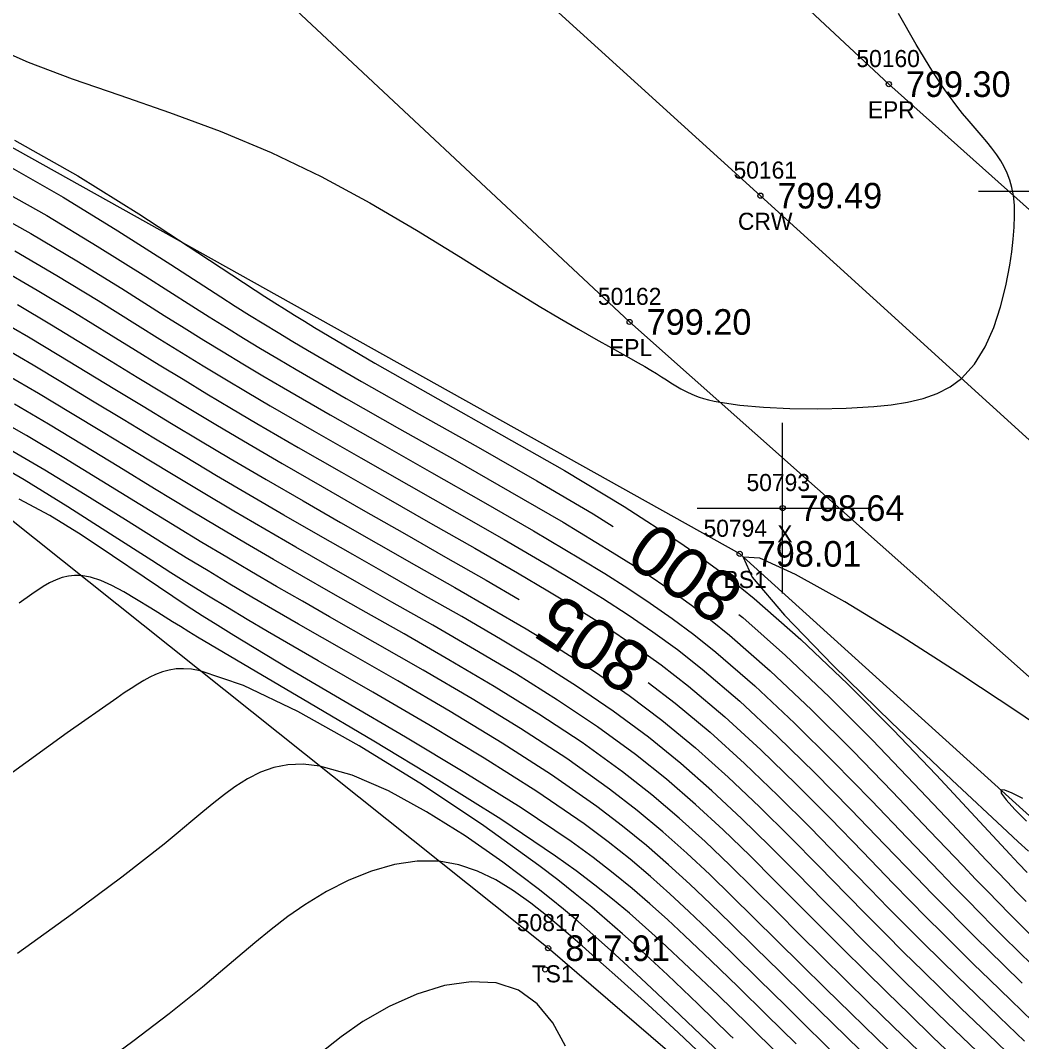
# Model space of a CAD drawing. Extents: x 1378535 to 1380697, y 997729 to 1000024.
# Drawn here: x 1378608.7 to 1378667.4, y 999849.2 to 999909.1 of the extents above; entities that cross this region are included whole.
import ezdxf

# ---------------------------------------------------------------- set-up
doc = ezdxf.new("R2010")
doc.units = 0
for name, color, linetype in [('RD_DTM_BkLn1', 7, 'Continuous'), ('RD_DTM_BkLn2', 7, 'Continuous'), ('RD_DTM_BkLn_txCode', 7, 'Continuous'), ('RD_DTM_Major1', 7, 'Continuous'), ('RD_DTM_Major1_Lbl', 7, 'Continuous'), ('RD_DTM_Minor1', 7, 'Continuous'), ('RD_EX_Misc', 7, 'Continuous'), ('RD_EX_Misc_txCode', 7, 'Continuous'), ('RD_EX_Road', 7, 'Continuous'), ('RD_EX_Road_txCode', 7, 'Continuous'), ('RD_EX_TX_Misc_ELEV', 7, 'Continuous'), ('RD_EX_TX_Road_ELEV', 7, 'Continuous'), ('RD_HC_Survey_ELEV', 7, 'Continuous'), ('RD_HC_Survey_txCode', 7, 'Continuous'), ('RD_SMD_Locator', 7, 'Continuous')]:
    doc.layers.add(name, color=color, linetype=linetype)

msp = doc.modelspace()

# ---------------------------------------------------------------- linework, layer by layer
at = {"layer": 'RD_DTM_BkLn1'}
msp.add_lwpolyline([(1379201.7, 999398.205), (1379156.533, 999438.891), (1379112.084, 999479.847), (1379066.495, 999520.561), (1379020.821, 999562.613), (1378974.239, 999604.981), (1378928.957, 999646.778), (1378882.739, 999688.619), (1378834.578, 999733.071), (1378787.698, 999775.121), (1378743.642, 999816.274), (1378698.706, 999856.431), (1378652.056, 999898.787), (1378607.023, 999939.646), (1378604.538, 999941.267)], dxfattribs=at)
at = {"layer": 'RD_DTM_BkLn2'}
for points in [[(1378760.972, 999750.758), (1378735.038, 999800.678), (1378693.628, 999839.142), (1378650.843, 999877.81), (1378599.986, 999906.202), (1378575.293, 999908.279)], [(1378753.21, 999744.316), (1378718.796, 999791.159), (1378676.682, 999822.843), (1378639.622, 999854.713), (1378600.054, 999886.249), (1378588.163, 999885.418), (1378551.81, 999886.228), (1378537.215, 999880.675)]]:
    msp.add_lwpolyline(points, dxfattribs=at)
at = {"layer": 'RD_DTM_Major1'}
for points in [[(1378607.923, 999900.565), (1378611.205, 999898.707), (1378614.415, 999896.737), (1378617.508, 999894.754), (1378620.441, 999892.862), (1378621.289, 999892.323), (1378622.128, 999891.797), (1378622.963, 999891.279), (1378623.804, 999890.765), (1378624.658, 999890.25), (1378625.532, 999889.73), (1378628.688, 999887.904), (1378632.057, 999886), (1378635.52, 999884.05), (1378638.958, 999882.089), (1378642.252, 999880.149), (1378643.423, 999879.421)], [(1378608.533, 999892.407), (1378610.521, 999891.23), (1378612.479, 999890.037), (1378614.016, 999889.096), (1378615.537, 999888.167), (1378617.058, 999887.242), (1378618.594, 999886.314), (1378620.161, 999885.376), (1378621.776, 999884.421), (1378624.039, 999883.101), (1378626.386, 999881.75), (1378628.785, 999880.378), (1378631.206, 999878.999), (1378633.617, 999877.624), (1378635.987, 999876.266), (1378637.925, 999875.145)], [(1378660.491, 999847.861), (1378658.882, 999849.416), (1378657.346, 999850.912), (1378655.87, 999852.358), (1378654.441, 999853.763), (1378653.048, 999855.139), (1378651.677, 999856.495), (1378650.392, 999857.762), (1378649.09, 999859.023), (1378647.747, 999860.279), (1378646.338, 999861.532), (1378644.838, 999862.784), (1378643.221, 999864.037), (1378640.707, 999865.815), (1378637.994, 999867.58), (1378635.164, 999869.313), (1378632.301, 999870.995), (1378629.489, 999872.606), (1378626.813, 999874.127), (1378625.232, 999875.029), (1378623.716, 999875.903), (1378622.243, 999876.76), (1378620.79, 999877.616), (1378619.337, 999878.483), (1378617.861, 999879.376), (1378615.692, 999880.707), (1378613.475, 999882.074), (1378611.251, 999883.432), (1378609.062, 999884.736), (1378606.949, 999885.941)], [(1378650.79, 999874.265), (1378651.025, 999874.073), (1378653.534, 999871.862), (1378656.093, 999869.426), (1378658.624, 999866.888), (1378661.052, 999864.368), (1378663.3, 999861.991), (1378665.292, 999859.877), (1378665.922, 999859.214), (1378666.518, 999858.592), (1378667.086, 999858.003), (1378667.635, 999857.44)], [(1378650.457, 999849.444), (1378650.275, 999849.622), (1378648.411, 999851.431), (1378646.608, 999853.148), (1378644.834, 999854.787), (1378643.968, 999855.564), (1378643.086, 999856.335), (1378642.172, 999857.11), (1378641.21, 999857.898), (1378640.184, 999858.709), (1378639.079, 999859.552), (1378635.856, 999861.871), (1378632.259, 999864.275), (1378628.545, 999866.574), (1378624.966, 999868.581), (1378621.779, 999870.106), (1378619.236, 999870.961), (1378618.724, 999871.049), (1378618.258, 999871.085), (1378617.826, 999871.069), (1378617.417, 999871.005), (1378617.019, 999870.895), (1378616.621, 999870.739), (1378616.286, 999870.58), (1378615.94, 999870.391), (1378615.577, 999870.176), (1378615.194, 999869.932), (1378614.787, 999869.662), (1378614.351, 999869.366), (1378611.445, 999867.325), (1378607.81, 999864.7)], [(1378645.487, 999870.273), (1378647.062, 999869.072), (1378649.115, 999867.357), (1378651.124, 999865.538), (1378653.079, 999863.663), (1378654.965, 999861.779), (1378656.77, 999859.933), (1378658.481, 999858.174), (1378659.55, 999857.083), (1378660.586, 999856.037), (1378661.601, 999855.022), (1378662.609, 999854.025), (1378663.621, 999853.032), (1378664.651, 999852.031), (1378666.061, 999850.672), (1378667.522, 999849.271)]]:
    msp.add_lwpolyline(points, dxfattribs=at)
at = {"layer": 'RD_DTM_Minor1'}
for points in [[(1378606.804, 999907.633), (1378609.149, 999906.606), (1378611.741, 999905.636), (1378614.521, 999904.673), (1378617.429, 999903.666), (1378620.405, 999902.566), (1378623.388, 999901.323), (1378626.323, 999899.905), (1378629.174, 999898.362), (1378631.908, 999896.763), (1378634.494, 999895.177), (1378636.899, 999893.673), (1378639.09, 999892.32), (1378640.288, 999891.607), (1378641.397, 999890.967), (1378642.415, 999890.392), (1378643.34, 999889.876), (1378644.17, 999889.413), (1378644.905, 999888.996), (1378645.284, 999888.775), (1378645.635, 999888.565), (1378645.96, 999888.368), (1378646.263, 999888.181), (1378646.547, 999888.003), (1378646.815, 999887.835), (1378647.011, 999887.713), (1378647.204, 999887.596), (1378647.395, 999887.484), (1378647.59, 999887.376), (1378647.789, 999887.274), (1378647.998, 999887.176), (1378648.223, 999887.082), (1378648.465, 999886.992), (1378648.729, 999886.908), (1378649.019, 999886.829), (1378649.34, 999886.754), (1378649.696, 999886.685), (1378650.854, 999886.521), (1378652.241, 999886.399), (1378653.787, 999886.324), (1378655.425, 999886.301), (1378657.085, 999886.337), (1378658.699, 999886.437), (1378659.72, 999886.544), (1378660.684, 999886.697), (1378661.585, 999886.912), (1378662.416, 999887.205), (1378663.171, 999887.59), (1378663.845, 999888.083), (1378664.609, 999888.92), (1378665.234, 999889.927), (1378665.735, 999891.059), (1378666.13, 999892.268), (1378666.434, 999893.507), (1378666.664, 999894.727), (1378666.781, 999895.499), (1378666.87, 999896.239), (1378666.928, 999896.943), (1378666.95, 999897.608), (1378666.935, 999898.229), (1378666.877, 999898.803), (1378666.79, 999899.268), (1378666.67, 999899.698), (1378666.519, 999900.1), (1378666.341, 999900.478), (1378666.136, 999900.838), (1378665.908, 999901.185), (1378665.625, 999901.566), (1378665.319, 999901.946), (1378664.99, 999902.332), (1378664.643, 999902.733), (1378664.28, 999903.155), (1378663.904, 999903.608), (1378663.63, 999903.951), (1378663.351, 999904.316), (1378663.065, 999904.705), (1378662.772, 999905.12), (1378662.471, 999905.564), (1378662.161, 999906.038), (1378661.188, 999907.636), (1378660.151, 999909.464)], [(1378608.358, 999902.033), (1378612.063, 999899.957), (1378615.64, 999897.73), (1378619.099, 999895.46), (1378622.45, 999893.256), (1378623.029, 999892.884), (1378623.606, 999892.517), (1378624.183, 999892.153), (1378624.763, 999891.791), (1378625.346, 999891.431), (1378625.935, 999891.072), (1378629.476, 999888.986), (1378633.164, 999886.891), (1378636.896, 999884.79), (1378640.57, 999882.685), (1378644.084, 999880.577), (1378647.335, 999878.47), (1378648.089, 999877.947), (1378648.825, 999877.421), (1378649.549, 999876.887), (1378650.263, 999876.341), (1378650.974, 999875.78), (1378651.685, 999875.2), (1378654.422, 999872.803), (1378657.161, 999870.198), (1378659.828, 999867.51), (1378662.35, 999864.867), (1378664.655, 999862.397), (1378666.67, 999860.226), (1378667.186, 999859.673), (1378667.678, 999859.151)], [(1378607.27, 999899.293), (1378610.26, 999897.619), (1378613.207, 999895.839), (1378616.052, 999894.047), (1378618.738, 999892.336), (1378619.764, 999891.69), (1378620.769, 999891.064), (1378621.767, 999890.45), (1378622.772, 999889.84), (1378623.799, 999889.226), (1378624.861, 999888.599), (1378627.78, 999886.915), (1378630.914, 999885.138), (1378634.153, 999883.309), (1378637.384, 999881.469), (1378640.497, 999879.657), (1378643.38, 999877.915), (1378644.609, 999877.142), (1378645.782, 999876.376), (1378646.915, 999875.6), (1378648.027, 999874.798), (1378649.132, 999873.953), (1378650.248, 999873.049), (1378652.626, 999870.965), (1378655.054, 999868.668), (1378657.466, 999866.266), (1378659.793, 999863.869), (1378661.97, 999861.587), (1378663.928, 999859.529), (1378664.662, 999858.765), (1378665.355, 999858.049), (1378666.017, 999857.372), (1378666.656, 999856.723), (1378667.282, 999856.095), (1378667.903, 999855.477)], [(1378606.59, 999898.08), (1378609.314, 999896.578), (1378612.017, 999894.972), (1378614.641, 999893.343), (1378617.13, 999891.775), (1378618.303, 999891.041), (1378619.448, 999890.331), (1378620.582, 999889.636), (1378621.726, 999888.944), (1378622.897, 999888.245), (1378624.115, 999887.529), (1378626.848, 999885.95), (1378629.773, 999884.285), (1378632.796, 999882.572), (1378635.824, 999880.848), (1378638.763, 999879.152), (1378641.52, 999877.52), (1378642.942, 999876.652), (1378644.299, 999875.795), (1378645.608, 999874.928), (1378646.89, 999874.029), (1378648.164, 999873.077), (1378649.447, 999872.052), (1378651.729, 999870.071), (1378654.045, 999867.899), (1378656.341, 999865.631), (1378658.563, 999863.36), (1378660.656, 999861.18), (1378662.567, 999859.185), (1378663.395, 999858.328), (1378664.181, 999857.523), (1378664.934, 999856.759), (1378665.664, 999856.025), (1378666.383, 999855.31), (1378667.1, 999854.603), (1378668.064, 999853.662)], [(1378608.378, 999895.556), (1378610.842, 999894.116), (1378613.252, 999892.641), (1378615.561, 999891.201), (1378616.866, 999890.389), (1378618.14, 999889.603), (1378619.404, 999888.831), (1378620.679, 999888.061), (1378621.985, 999887.282), (1378623.343, 999886.483), (1378625.912, 999884.995), (1378628.639, 999883.437), (1378631.451, 999881.838), (1378634.275, 999880.231), (1378637.04, 999878.644), (1378639.673, 999877.108), (1378641.278, 999876.151), (1378642.815, 999875.205), (1378644.302, 999874.247), (1378645.758, 999873.252), (1378647.2, 999872.198), (1378648.645, 999871.061), (1378650.847, 999869.172), (1378653.059, 999867.12), (1378655.24, 999864.984), (1378657.352, 999862.841), (1378659.353, 999860.769), (1378661.206, 999858.845), (1378662.121, 999857.903), (1378662.994, 999857.014), (1378663.836, 999856.165), (1378664.658, 999855.344), (1378665.472, 999854.539), (1378666.29, 999853.738), (1378667.395, 999852.665)], [(1378607.451, 999894.54), (1378609.68, 999893.263), (1378611.879, 999891.938), (1378614.013, 999890.621), (1378615.439, 999889.741), (1378616.838, 999888.882), (1378618.23, 999888.033), (1378619.634, 999887.185), (1378621.071, 999886.327), (1378622.561, 999885.448), (1378624.976, 999884.046), (1378627.51, 999882.591), (1378630.114, 999881.107), (1378632.736, 999879.614), (1378635.325, 999878.134), (1378637.83, 999876.689), (1378639.608, 999875.646), (1378641.325, 999874.611), (1378642.995, 999873.559), (1378644.63, 999872.467), (1378646.244, 999871.311), (1378647.85, 999870.068), (1378649.977, 999868.266), (1378652.087, 999866.332), (1378654.154, 999864.327), (1378656.154, 999862.313), (1378658.058, 999860.353), (1378659.844, 999858.508), (1378660.839, 999857.489), (1378661.795, 999856.519), (1378662.724, 999855.586), (1378663.639, 999854.678), (1378664.551, 999853.78), (1378665.473, 999852.881), (1378666.728, 999851.668), (1378668.025, 999850.422)], [(1378607.401, 999891.544), (1378609.178, 999890.514), (1378610.955, 999889.45), (1378612.594, 999888.457), (1378614.235, 999887.46), (1378615.886, 999886.458), (1378617.556, 999885.448), (1378619.254, 999884.429), (1378620.989, 999883.4), (1378623.101, 999882.163), (1378625.263, 999880.912), (1378627.463, 999879.651), (1378629.685, 999878.383), (1378631.918, 999877.112), (1378634.146, 999875.842), (1378636.248, 999874.636), (1378638.328, 999873.418), (1378640.378, 999872.169), (1378642.392, 999870.873), (1378644.362, 999869.513), (1378646.282, 999868.072), (1378648.257, 999866.444), (1378650.167, 999864.739), (1378652.009, 999862.993), (1378653.783, 999861.238), (1378655.486, 999859.509), (1378657.118, 999857.84), (1378658.255, 999856.685), (1378659.368, 999855.566), (1378660.468, 999854.47), (1378661.569, 999853.384), (1378662.684, 999852.293), (1378663.826, 999851.186), (1378665.397, 999849.674), (1378667.028, 999848.114)], [(1378664.735, 999848.676), (1378662.997, 999850.345), (1378661.741, 999851.562), (1378660.521, 999852.752), (1378659.326, 999853.929), (1378658.142, 999855.105), (1378656.957, 999856.293), (1378655.755, 999857.506), (1378654.207, 999859.08), (1378652.605, 999860.692), (1378650.942, 999862.319), (1378649.211, 999863.939), (1378647.402, 999865.53), (1378645.508, 999867.068), (1378643.435, 999868.601), (1378641.281, 999870.064), (1378639.07, 999871.466), (1378636.822, 999872.818), (1378634.56, 999874.132), (1378632.306, 999875.416), (1378630.228, 999876.597), (1378628.175, 999877.765), (1378626.146, 999878.924), (1378624.142, 999880.078), (1378622.16, 999881.23), (1378620.2, 999882.383), (1378618.351, 999883.487), (1378616.522, 999884.588), (1378614.716, 999885.682), (1378612.933, 999886.762), (1378611.174, 999887.823), (1378609.442, 999888.858), (1378607.853, 999889.789)], [(1378664.077, 999847.681), (1378662.168, 999849.512), (1378660.794, 999850.84), (1378659.469, 999852.131), (1378658.179, 999853.398), (1378656.912, 999854.652), (1378655.655, 999855.906), (1378654.394, 999857.172), (1378652.931, 999858.646), (1378651.431, 999860.14), (1378649.877, 999861.641), (1378648.255, 999863.137), (1378646.548, 999864.614), (1378644.74, 999866.061), (1378642.516, 999867.681), (1378640.177, 999869.246), (1378637.763, 999870.757), (1378635.313, 999872.216), (1378632.869, 999873.626), (1378630.47, 999874.989), (1378628.549, 999876.078), (1378626.675, 999877.146), (1378624.835, 999878.2), (1378623.019, 999879.251), (1378621.215, 999880.305), (1378619.412, 999881.374), (1378617.451, 999882.551), (1378615.492, 999883.737), (1378613.547, 999884.918), (1378611.632, 999886.075), (1378609.76, 999887.194), (1378607.944, 999888.257)], [(1378661.332, 999848.683), (1378659.84, 999850.125), (1378658.409, 999851.518), (1378657.026, 999852.874), (1378655.678, 999854.205), (1378654.351, 999855.521), (1378653.035, 999856.835), (1378651.66, 999858.207), (1378650.26, 999859.584), (1378648.813, 999860.961), (1378647.298, 999862.334), (1378645.693, 999863.699), (1378643.978, 999865.051), (1378641.607, 999866.753), (1378639.081, 999868.419), (1378636.46, 999870.041), (1378633.805, 999871.61), (1378631.177, 999873.118), (1378628.638, 999874.558), (1378626.883, 999875.555), (1378625.187, 999876.525), (1378623.532, 999877.479), (1378621.899, 999878.429), (1378620.271, 999879.389), (1378618.628, 999880.371), (1378616.56, 999881.623), (1378614.471, 999882.898), (1378612.388, 999884.166), (1378610.339, 999885.399), (1378608.354, 999886.568)], [(1378657.917, 999848.716), (1378656.278, 999850.313), (1378654.711, 999851.847), (1378653.205, 999853.326), (1378651.746, 999854.758), (1378650.322, 999856.151), (1378649.128, 999857.311), (1378647.923, 999858.456), (1378646.681, 999859.593), (1378645.377, 999860.728), (1378643.982, 999861.868), (1378642.471, 999863.019), (1378639.821, 999864.865), (1378636.921, 999866.727), (1378633.881, 999868.571), (1378630.808, 999870.368), (1378627.81, 999872.087), (1378624.995, 999873.696), (1378623.6, 999874.501), (1378622.266, 999875.279), (1378620.972, 999876.043), (1378619.698, 999876.807), (1378618.422, 999877.582), (1378617.122, 999878.382), (1378614.851, 999879.8), (1378612.504, 999881.263), (1378610.133, 999882.71), (1378607.787, 999884.08)], [(1378656.934, 999847.987), (1378653.55, 999851.33), (1378651.969, 999852.888), (1378650.446, 999854.377), (1378648.97, 999855.807), (1378647.868, 999856.858), (1378646.759, 999857.889), (1378645.618, 999858.907), (1378644.419, 999859.924), (1378643.134, 999860.949), (1378641.738, 999861.991), (1378638.96, 999863.893), (1378635.882, 999865.84), (1378632.635, 999867.792), (1378629.349, 999869.707), (1378626.154, 999871.546), (1378623.182, 999873.267), (1378621.984, 999873.973), (1378620.835, 999874.66), (1378619.72, 999875.337), (1378618.619, 999876.016), (1378617.517, 999876.706), (1378616.396, 999877.419), (1378613.989, 999878.969), (1378611.482, 999880.572), (1378608.928, 999882.145), (1378606.38, 999883.603)], [(1378654.149, 999849.104), (1378652.408, 999850.82), (1378650.748, 999852.446), (1378649.156, 999853.987), (1378647.618, 999855.449), (1378646.606, 999856.389), (1378645.588, 999857.306), (1378644.54, 999858.212), (1378643.438, 999859.117), (1378642.257, 999860.032), (1378640.972, 999860.969), (1378638.038, 999862.939), (1378634.748, 999864.991), (1378631.261, 999867.075), (1378627.736, 999869.141), (1378624.331, 999871.141), (1378621.206, 999873.024), (1378620.261, 999873.612), (1378619.356, 999874.187), (1378618.481, 999874.752), (1378617.627, 999875.313), (1378616.786, 999875.875), (1378615.949, 999876.441), (1378614.106, 999877.7), (1378612.259, 999878.931), (1378610.43, 999880.061), (1378608.636, 999881.017)], [(1378668.865, 999867.369), (1378667.146, 999868.531), (1378663.851, 999870.714), (1378660.358, 999872.946), (1378657, 999874.991), (1378654.109, 999876.61), (1378652.017, 999877.566), (1378651.054, 999877.619), (1378651.566, 999876.446), (1378653.46, 999874.212), (1378656.321, 999871.262), (1378659.732, 999867.936), (1378663.277, 999864.578), (1378666.541, 999861.53), (1378667.163, 999860.951), (1378667.757, 999860.399)], [(1378653.162, 999848.446), (1378651.323, 999850.258), (1378649.573, 999851.965), (1378647.892, 999853.573), (1378646.261, 999855.088), (1378645.325, 999855.931), (1378644.378, 999856.757), (1378643.399, 999857.577), (1378642.366, 999858.402), (1378641.258, 999859.243), (1378640.055, 999860.112), (1378636.846, 999862.267), (1378633.226, 999864.541), (1378629.416, 999866.839), (1378625.641, 999869.067), (1378622.123, 999871.131), (1378619.085, 999872.937), (1378618.571, 999873.249), (1378618.081, 999873.548), (1378617.615, 999873.834), (1378616.746, 999874.371), (1378616.341, 999874.622), (1378615.511, 999875.132), (1378614.753, 999875.578), (1378614.057, 999875.952), (1378613.413, 999876.244), (1378612.809, 999876.443), (1378612.235, 999876.54), (1378611.872, 999876.545), (1378611.513, 999876.503), (1378611.153, 999876.416), (1378610.789, 999876.284), (1378610.416, 999876.109), (1378610.029, 999875.892), (1378609.364, 999875.454), (1378608.637, 999874.914)], [(1378651.085, 999847.256), (1378648.963, 999849.268), (1378646.969, 999851.158), (1378645.077, 999852.934), (1378643.265, 999854.599), (1378642.583, 999855.213), (1378641.902, 999855.814), (1378641.215, 999856.409), (1378640.514, 999857), (1378639.793, 999857.593), (1378639.044, 999858.19), (1378636.976, 999859.752), (1378634.765, 999861.287), (1378632.498, 999862.706), (1378630.262, 999863.921), (1378628.146, 999864.842), (1378626.237, 999865.381), (1378625.264, 999865.488), (1378624.372, 999865.454), (1378623.543, 999865.291), (1378622.761, 999865.014), (1378622.008, 999864.635), (1378621.269, 999864.167), (1378620.659, 999863.725), (1378620.034, 999863.235), (1378619.381, 999862.696), (1378618.686, 999862.112), (1378617.938, 999861.484), (1378617.122, 999860.812), (1378614.65, 999858.88), (1378611.748, 999856.723), (1378608.524, 999854.395)], [(1378667.434, 999863.485), (1378666.809, 999863.798), (1378666.37, 999863.97), (1378666.146, 999863.98), (1378666.172, 999863.787), (1378666.459, 999863.398), (1378666.967, 999862.843), (1378667.655, 999862.148)], [(1378649.064, 999848.054), (1378647.267, 999849.748), (1378645.461, 999851.408), (1378643.697, 999852.999), (1378642.023, 999854.486), (1378641.609, 999854.851), (1378641.204, 999855.206), (1378640.804, 999855.554), (1378640.409, 999855.893), (1378640.016, 999856.225), (1378639.625, 999856.55), (1378638.615, 999857.348), (1378637.593, 999858.078), (1378636.552, 999858.713), (1378635.484, 999859.229), (1378634.381, 999859.6), (1378633.237, 999859.802), (1378631.948, 999859.808), (1378630.622, 999859.61), (1378629.279, 999859.233), (1378627.941, 999858.699), (1378626.629, 999858.034), (1378625.362, 999857.262), (1378624.366, 999856.564), (1378623.394, 999855.815), (1378622.428, 999855.022), (1378621.447, 999854.188), (1378620.432, 999853.321), (1378619.362, 999852.424), (1378617.419, 999850.873), (1378615.288, 999849.252), (1378612.985, 999847.556)], [(1378640.634, 999848.976), (1378639.889, 999850.335), (1378638.98, 999851.45), (1378637.885, 999852.247), (1378636.582, 999852.676), (1378635.119, 999852.753), (1378633.551, 999852.521), (1378631.932, 999852.025), (1378630.316, 999851.307), (1378628.758, 999850.412), (1378627.486, 999849.526), (1378626.275, 999848.558)]]:
    msp.add_lwpolyline(points, dxfattribs=at)
at = {"layer": 'RD_EX_Misc'}
for p, q in [((1378664.831, 999899.048), (1378674.831, 999899.048)), ((1378653.361, 999875.488), (1378653.361, 999885.488)), ((1378648.361, 999880.488), (1378658.361, 999880.488))]:
    msp.add_line(p, q, dxfattribs=at)
at = {"layer": 'RD_EX_Road'}
for points in [[(1379209.475, 999405.54), (1379163.997, 999446.485), (1379118.805, 999488.017), (1379074.408, 999528.841), (1379028.669, 999569.9), (1378981.979, 999612.718), (1378937.166, 999653.911), (1378890.129, 999696.785), (1378842.566, 999740.72), (1378794.879, 999783.075), (1378749.806, 999824.149), (1378706.231, 999863.66), (1378659.579, 999905.32), (1378614.058, 999947.757), (1378610.306, 999950.384)], [(1379194.921, 999391.17), (1379151.382, 999431.093), (1379105.356, 999472.756), (1379062.213, 999513.117), (1379014.238, 999555.894), (1378967.91, 999597.354), (1378922.421, 999639.979), (1378876.774, 999681.523), (1378827.896, 999726.217), (1378781.196, 999768.463), (1378736.445, 999808.724), (1378691.95, 999849.175), (1378644.395, 999891.391), (1378600.504, 999932.423), (1378598.568, 999933.73)]]:
    msp.add_lwpolyline(points, dxfattribs=at)
at = {"layer": 'RD_SMD_Locator'}
for centre in [(1378659.579, 999905.32), (1378652.056, 999898.787), (1378644.395, 999891.391), (1378653.361, 999880.488), (1378650.843, 999877.81), (1378639.622, 999854.713), (1378639.451, 999853.468)]:
    msp.add_circle(centre, 0.15, dxfattribs=at)

# ---------------------------------------------------------------- texts
at = {"layer": 'RD_DTM_BkLn_txCode'}
for s, p in [('50794', (1378648.725, 999878.81)), ('BS1', (1378649.898, 999875.81)), ('50817', (1378637.787, 999855.713)), ('TS1', (1378638.661, 999852.713))]:
    msp.add_text(s, height=1, dxfattribs=at).set_placement(p)
at = {"layer": 'RD_DTM_Major1_Lbl'}
for s, rotation, p in [('800', 145.0132, (1378651.257, 999875.976)), ('805', 147.20601, (1378645.861, 999871.961))]:
    msp.add_text(s, height=3, rotation=rotation, dxfattribs=at).set_placement(p)
at = {"layer": 'RD_EX_Misc_txCode'}
for s, p in [('50793', (1378651.243, 999881.488)), ('X', (1378653.046, 999878.488))]:
    msp.add_text(s, height=1, dxfattribs=at).set_placement(p)
at = {"layer": 'RD_EX_Road_txCode'}
for s, p in [('50160', (1378657.681, 999906.32)), ('EPR', (1378658.351, 999903.32)), ('50162', (1378642.537, 999892.391)), ('EPL', (1378643.19, 999889.391))]:
    msp.add_text(s, height=1, dxfattribs=at).set_placement(p)
at = {"layer": 'RD_EX_TX_Misc_ELEV'}
for s, p in [('798.64', (1378654.361, 999879.738)), ('798.01', (1378651.843, 999877.06)), ('817.91', (1378640.622, 999853.963))]:
    msp.add_text(s, height=1.5, dxfattribs=at).set_placement(p)
at = {"layer": 'RD_EX_TX_Road_ELEV'}
for s, p in [('799.30', (1378660.579, 999904.57)), ('799.20', (1378645.395, 999890.641))]:
    msp.add_text(s, height=1.5, dxfattribs=at).set_placement(p)
at = {"layer": 'RD_HC_Survey_ELEV'}
msp.add_text('799.49', height=1.5, dxfattribs=at).set_placement((1378653.056, 999898.037))
at = {"layer": 'RD_HC_Survey_txCode'}
for s, p in [('50161', (1378650.481, 999899.787)), ('CRW', (1378650.741, 999896.787))]:
    msp.add_text(s, height=1, dxfattribs=at).set_placement(p)

doc.saveas('drawing.dxf')
